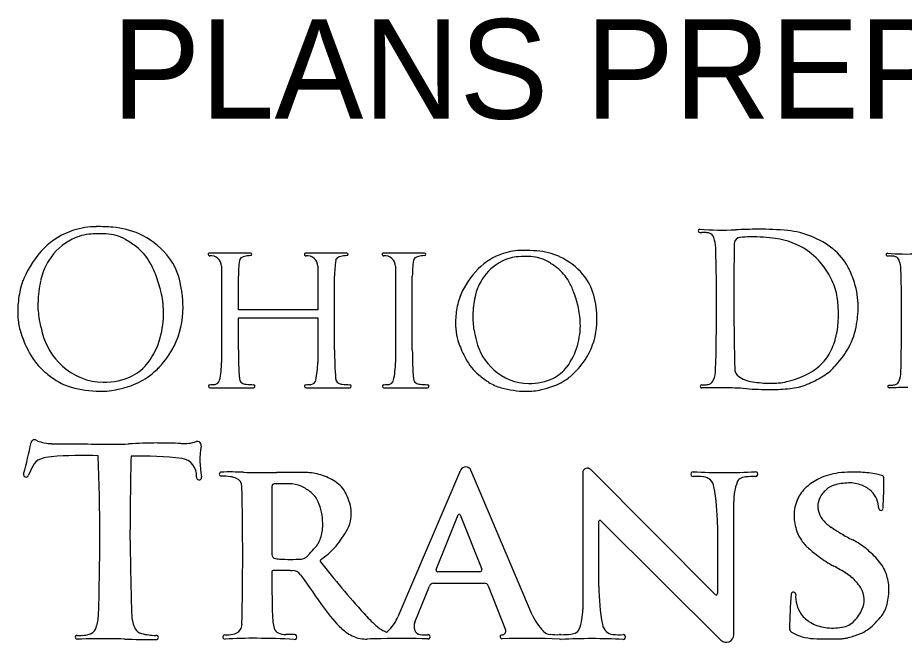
# Model space of a CAD drawing. Extents: x 0 to 34, y 0 to 22.
# Drawn here: x 3.091 to 4.337, y 1.379 to 2.257 of the extents above; entities that cross this region are included whole.
import ezdxf

# ---------------------------------------------------------------- set-up
doc = ezdxf.new("R2010")
doc.units = 0
doc.layers.add('SH_Text', color=7, linetype='Continuous')

msp = doc.modelspace()

# ---------------------------------------------------------------- linework, layer by layer
at = {"layer": 'SH_Text'}
for p, q in [((3.4178, 1.9264), (3.3603, 1.9264)), ((3.5531, 1.9264), (3.4956, 1.9264)), ((3.6624, 1.9264), (3.6049, 1.9264)), ((3.3771, 1.9079), (3.3771, 1.7726)), ((3.5123, 1.9079), (3.5123, 1.8464)), ((3.6216, 1.9079), (3.6216, 1.7726)), ((3.098, 1.8877), (3.098, 1.8877)), ((3.4007, 1.8464), (3.4007, 1.8938)), ((3.5359, 1.7903), (3.5359, 1.8938)), ((3.6453, 1.7903), (3.6453, 1.8938)), ((3.7124, 1.8652), (3.7124, 1.8652)), ((3.5123, 1.8464), (3.4007, 1.8464)), ((3.4007, 1.7903), (3.4007, 1.8354)), ((3.4007, 1.8354), (3.5123, 1.8354)), ((3.5123, 1.8354), (3.5123, 1.7726)), ((3.3607, 1.737), (3.422, 1.737)), ((3.4959, 1.737), (3.5573, 1.737)), ((3.6053, 1.737), (3.6666, 1.737)), ((3.7132, 1.6209), (3.6251, 1.415)), ((3.8139, 1.4178), (3.7276, 1.6209)), ((4.0712, 1.4464), (3.8961, 1.622)), ((3.8849, 1.6173), (3.8849, 1.4251)), ((4.0971, 1.3896), (4.0971, 1.5769)), ((3.6787, 1.4816), (3.7096, 1.5583)), ((3.7126, 1.5582), (3.7428, 1.4819)), ((3.9076, 1.4577), (3.9076, 1.5494)), ((3.9096, 1.5502), (4.0792, 1.3821)), ((3.2486, 1.5226), (3.2486, 1.5374)), ((4.0743, 1.5442), (4.0743, 1.4477)), ((3.7403, 1.4783), (3.681, 1.4783)), ((3.6752, 1.4621), (3.7466, 1.4621)), ((3.7521, 1.4583), (3.7764, 1.3967)), ((3.6488, 1.4074), (3.6692, 1.4581))]:
    msp.add_line(p, q, dxfattribs=at)
for centre, radius, start, end in [((3.1997, 1.8619), 0.1014, 107.613, 135.2994), ((3.2014, 1.8565), 0.107, 90.0889, 107.613), ((3.2017, 1.6667), 0.2969, 85.6243, 90.0889), ((3.216, 1.8529), 0.1101, 65.7405, 85.6243), ((4.0494, 1.9577), 0.0022, 85.6429, 267.986), ((4.0814, 2.3785), 0.4198, 265.6429, 272.4818), ((4.1424, 0.9717), 0.9883, 90.6415, 92.4818), ((4.1356, 1.5818), 0.3781, 84.3199, 90.6415), ((4.161, 1.8376), 0.1211, 51.3332, 84.3199), ((3.2047, 1.8713), 0.0835, 116.7026, 147.5385), ((3.1981, 1.8844), 0.0689, 93.5922, 116.7026), ((3.2064, 1.7523), 0.2013, 87.6816, 93.5922), ((3.2121, 1.894), 0.0595, 59.809, 87.6816), ((3.1732, 1.827), 0.1369, 52.0865, 59.809), ((3.2158, 1.8526), 0.1105, 40.354, 65.7405), ((4.0529, 2.0582), 0.1027, 267.986, 269.6056), ((4.0511, 1.8003), 0.1551, 87.8585, 89.6056), ((4.0561, 1.9345), 0.0209, 70.7604, 87.8585), ((4.0598, 1.945), 0.0098, 19.7623, 70.7604), ((4.0245, 1.9323), 0.0473, 1.7776, 19.7623), ((4.1066, 1.9397), 0.00866, 94.329, 166.7992), ((4.1316, 1.6097), 0.3397, 91.9186, 94.329), ((4.1253, 1.7966), 0.1526, 84.8974, 91.9186), ((4.0965, 1.4742), 0.4763, 82.8496, 84.8974), ((4.1432, 1.8462), 0.1014, 55.5454, 82.8496), ((3.2239, 1.838), 0.1354, 135.2994, 157.2066), ((3.2098, 1.8741), 0.0773, 29.7562, 52.0865), ((1.2277, 1.8509), 2.8453, 358.2224, 1.6678), ((7.761, 1.8671), 3.6638, 178.862, 181.6334), ((4.1066, 1.9397), 0.00866, 166.7992, 178.862), ((4.1854, 1.8681), 0.0821, 27.6817, 51.3332), ((3.2345, 1.8684), 0.086, 14.436, 40.354), ((3.3603, 1.9244), 0.00203, 90, 277.32), ((3.3624, 1.9079), 0.0146, 0, 97.32), ((3.408, 1.915), 0.00585, 114.8736, 172.0456), ((3.4157, 1.8984), 0.0242, 95.8947, 114.8736), ((3.4311, 1.7494), 0.174, 94.3316, 95.8947), ((3.4178, 1.9246), 0.00179, 274.3316, 90), ((3.4956, 1.9244), 0.00203, 90, 277.32), ((3.4977, 1.9079), 0.0146, 0, 97.32), ((3.5433, 1.915), 0.00585, 114.8736, 172.0456), ((3.551, 1.8984), 0.0242, 95.8947, 114.8736), ((3.5664, 1.7494), 0.174, 94.3316, 95.8947), ((3.5531, 1.9246), 0.00179, 274.3316, 90), ((3.6049, 1.9244), 0.00203, 90, 277.32), ((3.607, 1.9079), 0.0146, 0, 97.32), ((3.6526, 1.915), 0.00585, 114.8736, 172.0456), ((3.6603, 1.8984), 0.0242, 95.8947, 114.8736), ((3.6757, 1.7494), 0.174, 94.3316, 95.8947), ((3.6624, 1.9246), 0.00179, 274.3316, 90), ((3.7994, 1.8431), 0.0867, 107.613, 135.2994), ((3.798, 1.8624), 0.0589, 93.5922, 116.7026), ((3.8009, 1.8385), 0.0916, 90.0889, 107.613), ((3.8051, 1.7493), 0.1722, 87.6816, 93.5922), ((3.8011, 1.6761), 0.254, 85.6243, 90.0889), ((3.81, 1.8706), 0.0509, 59.809, 87.6816), ((3.8133, 1.8355), 0.0942, 65.7405, 85.6243), ((3.8132, 1.8352), 0.0945, 40.354, 65.7405), ((4.1454, 1.8495), 0.0974, 36.7351, 55.5454), ((4.3132, 1.9242), 0.00186, 85.6429, 267.986), ((4.3161, 2.0093), 0.087, 267.986, 269.6056), ((4.3403, 2.2808), 0.3557, 265.6429, 272.4818), ((4.3146, 1.7908), 0.1315, 87.8585, 89.6056), ((4.3189, 1.9045), 0.0177, 70.7604, 87.8585), ((4.322, 1.9134), 0.00831, 19.7623, 70.7604), ((3.2047, 1.8713), 0.0835, 147.5385, 165.5071), ((3.1801, 1.8571), 0.1115, 20.2973, 29.7562), ((3.5596, 1.8938), 0.1589, 172.0456, 180), ((3.6949, 1.8938), 0.1589, 172.0456, 180), ((3.8042, 1.8938), 0.1589, 172.0456, 180), ((3.8036, 1.8512), 0.0714, 116.7026, 147.5385), ((3.7767, 1.8133), 0.1171, 52.0865, 59.809), ((4.1327, 1.84), 0.1133, 23.505, 36.7351), ((4.2921, 1.9026), 0.0401, 1.7776, 19.7623), ((3.0825, 1.821), 0.2156, 13.7527, 20.2973), ((3.8201, 1.8227), 0.1159, 135.2994, 157.2066), ((3.8081, 1.8535), 0.0661, 29.7562, 52.0865), ((3.8291, 1.8487), 0.0736, 14.436, 40.354), ((4.1478, 1.8484), 0.1245, 17.0568, 27.6817), ((1.922, 1.8337), 2.4112, 358.2224, 1.6678), ((3.1724, 1.8583), 0.0801, 158.442, 167.8164), ((3.2239, 1.838), 0.1354, 157.2066, 158.442), ((3.2852, 1.8522), 0.1662, 167.8795, 178.2857), ((3.2463, 1.8606), 0.1265, 165.5071, 167.8795), ((3.1566, 1.8484), 0.1664, 0.6253, 14.436), ((3.8036, 1.8512), 0.0714, 147.5385, 165.5071), ((3.7826, 1.839), 0.0954, 20.2973, 29.7562), ((4.1585, 1.8512), 0.0852, 6.7275, 23.505), ((4.156, 1.8509), 0.116, 0.2266, 17.0568), ((3.2549, 1.8405), 0.1645, 167.8164, 176.8679), ((3.167, 1.8417), 0.1286, 1.1426, 13.7527), ((3.6991, 1.8081), 0.1844, 13.7527, 20.2973), ((3.2334, 1.8538), 0.1145, 178.2857, 190.5998), ((3.7761, 1.8401), 0.0685, 158.442, 167.8164), ((3.8201, 1.8227), 0.1159, 157.2066, 158.442), ((3.8725, 1.8349), 0.1422, 167.8795, 178.2857), ((3.8393, 1.842), 0.1082, 165.5071, 167.8795), ((3.7625, 1.8316), 0.1424, 0.6253, 14.436), ((4.0545, 1.8389), 0.1899, 0.6041, 6.7275), ((3.1972, 1.8437), 0.1067, 176.8679, 187.4835), ((3.2048, 1.8489), 0.1182, 333.1433, 0.6253), ((3.8466, 1.8248), 0.1407, 167.8164, 176.8679), ((3.7714, 1.8258), 0.11, 1.1426, 13.7527), ((4.1266, 1.8508), 0.1454, 348.6268, 0.2266), ((3.3908, 1.8832), 0.2746, 190.5998, 194.5022), ((3.1676, 1.8417), 0.1279, 344.2873, 1.1426), ((3.7973, 1.8275), 0.0913, 176.8679, 187.4835), ((3.8282, 1.8362), 0.0979, 178.2857, 190.5998), ((3.8038, 1.832), 0.1011, 333.1433, 0.6253), ((4.1094, 1.8395), 0.135, 349.9228, 0.6041), ((3.183, 1.8418), 0.0923, 187.4835, 199.5864), ((3.772, 1.8258), 0.1095, 344.2873, 1.1426), ((4.171, 1.8418), 0.1001, 328.8631, 348.6268), ((3.2618, 1.8698), 0.176, 199.5864, 208.6065), ((3.2175, 1.8384), 0.0956, 194.5022, 227.8932), ((3.7851, 1.8259), 0.0789, 187.4835, 199.5864), ((3.9629, 1.8614), 0.2349, 190.5998, 194.5022), ((4.1335, 1.8352), 0.1106, 337.2804, 349.9228), ((3.1889, 1.8357), 0.1059, 323.2967, 344.2873), ((3.1978, 1.8524), 0.126, 316.7511, 333.1433), ((3.8525, 1.8499), 0.1505, 199.5864, 208.6065), ((3.8146, 1.823), 0.0818, 194.5022, 227.8932), ((3.7901, 1.8207), 0.0906, 323.2967, 344.2873), ((3.1909, 1.8312), 0.0952, 208.6065, 229.3453), ((3.9256, 1.7903), 0.5249, 180, 184.4616), ((4.0608, 1.7903), 0.5249, 180, 184.4616), ((4.1702, 1.7903), 0.5249, 180, 184.4616), ((3.7978, 1.835), 0.1078, 316.7511, 333.1433), ((4.174, 1.8182), 0.0666, 316.2141, 337.2804), ((4.136, 1.863), 0.141, 316.6969, 328.8631), ((3.2238, 1.8097), 0.0623, 296.3448, 323.2967), ((3.2595, 1.7726), 0.1175, 347.6428, 360), ((3.3948, 1.7726), 0.1175, 347.6428, 360), ((3.5041, 1.7726), 0.1175, 347.6428, 360), ((3.7919, 1.8168), 0.0815, 208.6065, 229.3453), ((4.163, 1.8288), 0.0819, 297.1175, 316.2141), ((3.2164, 1.8609), 0.1343, 229.3453, 237.7571), ((3.2126, 1.8329), 0.0882, 227.8932, 268.7516), ((3.215, 1.8364), 0.1025, 306.2827, 316.7511), ((3.8104, 1.8184), 0.0755, 227.8932, 268.7516), ((3.82, 1.7984), 0.0533, 296.3448, 323.2967), ((3.8124, 1.8213), 0.0877, 306.2827, 316.7511), ((4.0244, 1.7641), 0.0473, 340.2377, 358.2224), ((4.1105, 1.763), 0.0118, 181.6334, 198.7573), ((4.1105, 1.763), 0.0118, 198.7573, 233.0825), ((4.1788, 1.8226), 0.0821, 301.0688, 316.6969), ((4.292, 1.7602), 0.0401, 340.2377, 358.2224), ((3.1875, 1.815), 0.0801, 237.7571, 254.2366), ((3.2126, 1.8324), 0.0877, 268.7516, 296.3448), ((3.2173, 1.8332), 0.0986, 289.5494, 306.2827), ((3.3672, 1.749), 0.00731, 275.8469, 347.6428), ((3.4093, 1.75), 0.00704, 184.4616, 238.9441), ((3.5024, 1.749), 0.00731, 275.8469, 347.6428), ((3.5446, 1.75), 0.00704, 184.4616, 238.9441), ((3.6118, 1.749), 0.00731, 275.8469, 347.6428), ((3.6539, 1.75), 0.00704, 184.4616, 238.9441), ((3.8137, 1.8423), 0.1149, 229.3453, 237.7571), ((3.7889, 1.803), 0.0686, 237.7571, 254.2366), ((3.8104, 1.8179), 0.075, 268.7516, 296.3448), ((3.8144, 1.8186), 0.0844, 289.5494, 306.2827), ((4.0596, 1.7515), 0.0098, 289.2396, 340.2377), ((4.1296, 1.7884), 0.0435, 233.0825, 262.024), ((4.1518, 1.9472), 0.2039, 262.024, 269.0831), ((4.1502, 1.8439), 0.1006, 269.0831, 282.4077), ((4.1463, 1.8613), 0.1184, 282.4077, 297.1175), ((4.1447, 1.8792), 0.1481, 292.086, 301.0688), ((4.3219, 1.7494), 0.00831, 289.2396, 340.2377), ((3.2083, 1.8889), 0.1569, 254.2366, 269.1033), ((3.2075, 1.8378), 0.1058, 269.1033, 283.3048), ((3.1914, 1.9061), 0.176, 283.3048, 289.5494), ((3.3607, 1.7391), 0.00215, 91.3892, 270), ((3.3584, 1.8353), 0.094, 271.3892, 275.8469), ((3.413, 1.7561), 0.0142, 238.9441, 264.1674), ((3.429, 1.9126), 0.1715, 264.1674, 267.7015), ((3.422, 1.7391), 0.00214, 270, 87.7015), ((3.4959, 1.7391), 0.00215, 91.3892, 270), ((3.4936, 1.8353), 0.094, 271.3892, 275.8469), ((3.5482, 1.7561), 0.0142, 238.9441, 264.1674), ((3.5642, 1.9126), 0.1715, 264.1674, 267.7015), ((3.5573, 1.7391), 0.00214, 270, 87.7015), ((3.6053, 1.7391), 0.00215, 91.3892, 270), ((3.6029, 1.8353), 0.094, 271.3892, 275.8469), ((3.6576, 1.7561), 0.0142, 238.9441, 264.1674), ((3.6735, 1.9126), 0.1715, 264.1674, 267.7015), ((3.6666, 1.7391), 0.00214, 270, 87.7015), ((3.8068, 1.8663), 0.1343, 254.2366, 269.1033), ((3.8061, 1.8225), 0.0905, 269.1033, 283.3048), ((3.7923, 1.8809), 0.1505, 283.3048, 289.5494), ((4.052, 1.7389), 0.00208, 90.3944, 271.2938), ((4.051, 1.8961), 0.1551, 270.3944, 272.1415), ((4.0767, 0.6483), 1.0888, 89.661, 91.2938), ((4.056, 1.762), 0.0209, 272.1415, 289.2396), ((4.0805, 1.2933), 0.4437, 85.604, 89.661), ((4.1483, 2.176), 0.4415, 265.604, 270.141), ((4.1488, 2.0041), 0.2696, 270.141, 275.8096), ((4.1671, 1.8241), 0.0887, 275.8096, 292.086), ((4.3154, 1.7387), 0.00177, 90.3944, 271.2943), ((4.3145, 1.872), 0.1315, 270.3944, 272.1415), ((4.3363, 0.8145), 0.9227, 89.661, 91.2938), ((4.3188, 1.7583), 0.0177, 272.1415, 289.2396), ((3.7204, 1.6179), 0.00783, 23.0123, 156.8357), ((3.8915, 1.6173), 0.00659, 44.9226, 180), ((3.3766, 1.6156), 0.00277, 91.4058, 270.3836), ((3.3883, 1.1401), 0.4785, 87.6467, 91.4058), ((3.3772, 1.5241), 0.0887, 81.9841, 90.3836), ((3.3849, 1.5785), 0.0338, 66.7153, 81.9841), ((3.3933, 1.5981), 0.0125, 1.1899, 66.7153), ((3.4269, 2.0806), 0.4628, 267.6467, 269.8791), ((3.4304, 3.7281), 2.1103, 269.8791, 270.6468), ((3.4772, -0.4208), 2.0388, 90.0211, 90.6468), ((3.4768, 0.595), 1.023, 88.946, 90.0211), ((3.4943, 1.5433), 0.0745, 72.6597, 88.946), ((3.4907, 1.5319), 0.0865, 57.7357, 72.6597), ((4.0402, 1.6155), 0.00341, 87.2578, 273.9158), ((4.0839, 2.5287), 0.9109, 267.2578, 272.7422), ((4.0466, 1.5223), 0.09, 84.7112, 93.9158), ((4.0534, 1.5966), 0.0154, 44.6622, 84.7112), ((4.11, 1.6015), 0.00857, 121.0781, 160.0072), ((4.1154, 1.5925), 0.0191, 94.7322, 121.0781), ((4.1286, 1.4339), 0.1783, 90.2807, 94.7322), ((4.1277, 1.6155), 0.00337, 270.2807, 92.7422), ((4.2484, 1.543), 0.0732, 114.943, 132.4657), ((4.2566, 1.5254), 0.0926, 97.7579, 114.943), ((4.2641, 1.4707), 0.1478, 90.9607, 97.7579), ((4.265, 1.4179), 0.2006, 84.4389, 90.9607), ((4.2725, 1.4953), 0.1228, 74.3106, 84.4389), ((4.3048, 1.6105), 0.0032, 1.4094, 74.3106), ((3.8165, 1.5985), 0.4916, 356.3798, 1.4094), ((-1.3032, 1.5005), 4.71, 358.826, 1.1899), ((7.1746, 1.5521), 3.727, 179.2885, 180.7309), ((3.4514, 1.5983), 0.00359, 90.1463, 179.2885), ((3.4617, -2.4289), 4.0309, 89.8537, 90.1463), ((3.4719, 1.5596), 0.0424, 66.3861, 89.8537), ((3.4635, 1.5404), 0.0633, 51.3513, 66.3861), ((3.5147, 1.5699), 0.0416, 25.2881, 57.7357), ((4.0513, 1.5944), 0.0184, 10.4886, 44.6622), ((3.78, 1.5442), 0.2943, 0, 10.4886), ((4.1776, 1.5769), 0.0805, 160.0072, 180), ((4.2343, 1.5585), 0.0522, 132.4657, 155.3011), ((4.2445, 1.5765), 0.0244, 105.0764, 133.1374), ((4.262, 1.5118), 0.0914, 92.1779, 105.0764), ((4.2602, 1.5584), 0.0448, 67.6502, 92.1779), ((4.2593, 1.5562), 0.0472, 47.6927, 67.6502), ((3.4821, 1.5637), 0.0335, 22.8398, 51.3513), ((3.4604, 1.5442), 0.1016, 17.375, 25.2881), ((4.2397, 1.5716), 0.0242, 151.3698, 183.6624), ((4.2453, 1.5685), 0.0306, 135.8422, 151.3698), ((4.3208, 1.4951), 0.1359, 133.1374, 135.8422), ((4.2731, 1.5714), 0.0266, 19.659, 47.6927), ((3.4376, 1.5449), 0.0818, 1.0904, 22.8398), ((3.5136, 1.5609), 0.0459, 1.6695, 17.375), ((4.2346, 1.5583), 0.0526, 155.3011, 180.5655), ((4.2415, 1.5601), 0.0602, 6.849, 19.659), ((3.506, 1.5607), 0.0535, 347.6719, 1.6695), ((3.7111, 1.5576), 0.00165, 21.558, 158.0768), ((4.2689, 1.5734), 0.0536, 183.6624, 190.7584), ((4.2414, 1.5682), 0.0255, 190.7584, 218.1063), ((4.3042, 1.5676), 0.00297, 186.849, 356.3798), ((3.4524, 1.5452), 0.067, 344.7965, 1.0904), ((3.5136, 1.559), 0.0457, 328.0388, 347.6719), ((3.9088, 1.5494), 0.00116, 45.2517, 180), ((4.2566, 1.5585), 0.0746, 180.5655, 198.551), ((4.2617, 1.5841), 0.0513, 218.1063, 236.7363), ((3.2661, 1.7134), 0.3374, 325.5456, 328.0388), ((4.2281, 1.549), 0.0444, 198.551, 216.4094), ((4.534, 1.9993), 0.5478, 236.7363, 238.5092), ((3.4788, 1.538), 0.0396, 332.9748, 344.7965), ((3.4675, 1.5752), 0.0932, 317.1015, 325.5456), ((4.2547, 1.5686), 0.0776, 216.4094, 227.4631), ((4.3643, 1.7223), 0.223, 238.5092, 243.3553), ((4.217, 1.4286), 0.1056, 50.847, 63.3553), ((3.2303, 1.7575), 0.371, 316.7489, 318.7344), ((3.4826, 1.5361), 0.0354, 318.7344, 332.9748), ((3.4525, 1.5892), 0.1137, 304.4843, 317.1015), ((4.3274, 1.6479), 0.1851, 227.4631, 233.2852), ((4.1995, 1.4071), 0.1332, 40.5298, 50.847), ((3.4698, 1.5048), 0.0219, 180.7309, 190.7021), ((3.4525, 1.5016), 0.00432, 190.7021, 253.7489), ((3.4608, 1.5301), 0.0341, 253.7489, 266.2417), ((3.4739, 1.7287), 0.233, 266.2417, 273.7583), ((3.4883, 1.5089), 0.0128, 273.7583, 316.5551), ((2.5785, 2.3706), 1.2659, 316.5551, 316.7489), ((4.3123, 1.6276), 0.1598, 233.2852, 242.187), ((3.5182, 1.4935), 0.00238, 124.4843, 218.1967), ((4.6112, 2.3535), 1.3932, 218.1967, 222.0923), ((4.1244, 1.2715), 0.2428, 57.2732, 62.187), ((4.2562, 1.4556), 0.0587, 17.0799, 40.5298), ((6.1948, 1.4707), 2.7469, 179.8417, 180.845), ((3.4496, 1.4783), 0.00162, 92.2725, 179.8417), ((3.4616, 1.1756), 0.3046, 87.7275, 92.2725), ((3.4753, 1.5206), 0.0407, 267.7275, 271.6845), ((3.4769, 1.4661), 0.0138, 35.1607, 91.6845), ((68.8439, 47.5104), 79.942, 215.160708, 215.20209), ((3.681, 1.4807), 0.00242, 158.0768, 270), ((3.7403, 1.481), 0.00266, 270, 21.558), ((4.221, 1.4217), 0.0642, 48.7163, 57.2732), ((4.2453, 1.4522), 0.0701, 0.0493, 17.0799), ((3.6752, 1.4557), 0.00637, 90, 158.0768), ((3.7466, 1.4562), 0.00592, 21.558, 90), ((4.2086, 1.4076), 0.083, 43.0442, 48.7163), ((4.2303, 1.4278), 0.0533, 31.4742, 43.0442), ((4.2019, 1.4577), 0.2943, 180, 190.4886), ((4.0725, 1.4477), 0.0018, 224.9226, 0), ((4.7475, 1.3941), 0.5719, 174.7189, 179.5985), ((4.1812, 1.4465), 0.00313, 356.1283, 174.7189), ((4.2273, 1.4434), 0.0431, 176.1283, 195.2204), ((4.2487, 1.4391), 0.0317, 1.1907, 31.4742), ((4.2391, 1.4522), 0.0762, 342.8982, 0.0493), ((4.2463, 1.4391), 0.0341, 337.5392, 1.1907), ((3.7463, 1.4346), 0.2981, 180.845, 185.1424), ((3.682, 1.5402), 0.1965, 215.2021, 226.1984), ((3.8044, 1.4251), 0.0805, 340.0072, 0), ((4.2261, 1.4431), 0.0419, 195.2204, 215.9003), ((4.2286, 1.4464), 0.0533, 315.6317, 337.5392), ((4.2704, 1.4426), 0.0435, 318.5081, 342.8982), ((3.7836, 1.6059), 0.2779, 222.0923, 226.9231), ((3.5696, 1.4387), 0.0604, 316.4579, 336.8357), ((3.8805, 1.4461), 0.0723, 203.0123, 225.1414), ((4.2256, 1.4427), 0.0413, 215.9003, 240.5772), ((4.2443, 1.4311), 0.0313, 279.4993, 315.6317), ((4.1144, 1.5807), 0.2519, 315.3471, 318.5081), ((3.268, 1.4049), 0.0139, 208.8899, 256.1998), ((3.3908, 1.4058), 0.0155, 277.2409, 324.471), ((3.3929, 1.4043), 0.013, 324.471, 358.826), ((3.5028, 1.4127), 0.0536, 185.1424, 195.487), ((3.4602, 1.4009), 0.00935, 195.487, 247.0071), ((3.5852, 1.4393), 0.0567, 226.1984, 246.9317), ((3.6255, 1.4368), 0.0464, 226.9231, 246.826), ((3.5912, 1.4182), 0.0306, 305.8215, 316.4579), ((3.664, 1.4013), 0.0163, 158.0768, 199.4864), ((3.7715, 1.3948), 0.00528, 269.2063, 21.558), ((3.872, 1.4005), 0.00857, 301.0781, 340.0072), ((3.9307, 1.4075), 0.0184, 190.4886, 224.6622), ((4.1812, 1.3981), 0.00555, 179.5985, 239.6518), ((4.2338, 1.4571), 0.0578, 240.5772, 262.1154), ((4.2365, 1.4773), 0.0782, 262.1154, 279.4993), ((4.2537, 1.443), 0.056, 291.4072, 304.2944), ((4.2539, 1.4428), 0.0557, 304.2944, 315.3471), ((3.2854, 1.476), 0.0872, 256.1998, 269.6084), ((3.3818, 1.3866), 0.00294, 91.9437, 273.1058), ((3.3777, 1.5089), 0.1195, 271.9437, 277.2409), ((3.4237, 0.6151), 0.7696, 89.7765, 93.1058), ((3.4229, 0.4222), 0.9625, 86.6437, 89.7765), ((3.4673, 1.4177), 0.0276, 247.0071, 270.3611), ((3.4699, 1.0077), 0.3823, 88.547, 90.3611), ((3.4795, 1.3865), 0.00344, 266.6437, 88.547), ((3.5801, 1.4273), 0.0437, 246.9317, 272.1689), ((3.5988, 0.9339), 0.4501, 89.6565, 92.1689), ((3.6323, 0.6389), 0.7457, 87.3132, 92.3652), ((3.6294, 1.4461), 0.0564, 246.826, 248.887), ((3.6571, 1.3989), 0.00903, 199.4864, 265.9434), ((3.6624, 1.4739), 0.0843, 265.9434, 273.2347), ((3.6674, 1.3868), 0.00302, 267.3132, 93.2347), ((3.7714, 1.3868), 0.00277, 89.2063, 271.9867), ((3.8079, 0.3357), 1.0489, 87.5828, 91.9867), ((3.8408, 1.4062), 0.0161, 225.1414, 263.7877), ((3.8484, 1.4766), 0.0868, 263.7877, 272.4172), ((3.8522, 1.3868), 0.00307, 71.2853, 92.4172), ((3.8522, 1.3868), 0.00307, 267.5828, 272.692), ((3.8543, 1.3865), 0.00337, 235.6638, 272.7422), ((3.8543, 1.3865), 0.00337, 90.2807, 108.3135), ((3.8534, 1.5681), 0.1783, 270.2807, 274.7322), ((3.898, 0.4733), 0.9109, 87.2578, 92.7422), ((3.8665, 1.4095), 0.0191, 274.7322, 301.0781), ((3.9285, 1.4054), 0.0154, 224.6622, 264.7112), ((3.9354, 1.4797), 0.09, 264.7112, 273.9158), ((3.9418, 1.3865), 0.00341, 267.2578, 93.9158), ((4.0866, 1.3896), 0.0105, 225.2517, 0), ((4.2117, 1.4502), 0.0659, 239.6518, 267.9533), ((4.234, 2.0737), 0.6899, 267.9533, 271.0092), ((4.2453, 1.4288), 0.0448, 271.0092, 278.9688), ((4.2427, 1.4456), 0.0619, 278.9688, 284.1635), ((4.2246, 1.5175), 0.1359, 284.1635, 291.4072)]:
    msp.add_arc(centre, radius, start, end, dxfattribs=at)
for centre, major_axis, ratio, start_param, end_param in [((2.4001, 1.8312), (-0.0048, 0.7768), 0.935925, 4.426098, 4.484451), ((3.1139, 1.659), (-0.00003, 0.005), 0.935925, 5.701972, 7.626044), ((3.1205, 1.6698), (-0.00005, 0.00788), 0.935925, 2.560379, 2.782597), ((3.1386, 1.7225), (-0.0004, 0.064), 0.935925, 2.782597, 3.125908), ((3.2685, 17.117), (-0.0965, 15.4591), 0.935925, 3.125908, 3.132143), ((3.2293, 2.068), (-0.0026, 0.4103), 0.935925, 3.132143, 3.178667), ((3.3019, 0.2971), (-0.0085, 1.3623), 0.935925, 0.004955, 0.037075), ((3.2927, 1.1381), (-0.0033, 0.5212), 0.935925, 6.220389, 6.28814), ((3.3235, 1.7228), (-0.0004, 0.0644), 0.935925, 3.078796, 3.439371), ((3.3431, 1.6561), (0.00003, -0.00555), 0.935925, 1.393395, 3.439371), ((3.4551, 1.6353), (-0.0007, 0.1158), 0.935925, 1.393395, 1.768582), ((3.1284, 1.6173), (-0.0001, 0.0203), 0.935925, 0.316985, 1.084293), ((3.1431, 1.5705), (-0.0004, 0.0697), 0.935925, 0.075388, 0.316985), ((3.181, 1.0792), (-0.0035, 0.5626), 0.935925, 6.233364, 6.358573), ((-1.1066, 1.5247), (4.3126, 0), 0.815575, 6.25216, 6.316325), ((8.8019, 1.5447), (5.5533, 0), 0.815575, 3.120359, 3.143198), ((3.2618, 1.0653), (-0.0036, 0.5757), 0.935925, 6.16473, 6.298779), ((3.3194, 1.6134), (-0.0002, 0.0241), 0.935925, 4.624066, 6.16473), ((3.4763, 1.4236), (-0.0027, 0.4393), 0.935925, 1.084293, 1.117953), ((3.1022, 1.6151), (-0.00002, 0.00377), 0.935925, 1.284505, 4.259546), ((3.3454, 1.6111), (-0.00002, 0.0038), 0.935925, 1.482474, 4.910175), ((8.8019, 1.5447), (5.5533, 0), 0.815575, 3.146466, 3.170101), ((3.1323, 1.4174), (0.0717, 0), 0.815575, 5.938269, 6.25216), ((3.3068, 1.4169), (-0.056, 0), 0.815575, 0.028508, 0.422883), ((3.1858, 1.4017), (0.0149, 0), 0.815575, 5.048183, 5.938269), ((3.1743, 1.3862), (0.00316, 0), 0.815575, 1.57768, 4.734978), ((3.1726, 1.5805), (-0.2351, 0), 0.815575, 1.57768, 1.608173), ((3.2116, 0.038), (1.6503, 0), 0.815575, 1.564879, 1.593377), ((3.1802, 1.4147), (-0.0317, 0), 0.815575, 1.608173, 1.90659), ((3.2174, 0.8354), (0.6726, 0), 0.815575, 1.536477, 1.564879), ((3.286, 2.4653), (1.3271, 0), 0.815575, 4.67807, 4.711475), ((3.2848, 1.3859), (0.0036, 0), 0.815575, 4.711475, 7.845601)]:
    msp.add_ellipse(centre, major_axis=major_axis, ratio=ratio, start_param=start_param, end_param=end_param, dxfattribs=at)

# ---------------------------------------------------------------- texts
msp.add_text('PLANS PREPARED BY:', height=0.14, dxfattribs=at).set_placement((3.2226, 2.1153))

doc.saveas('drawing.dxf')
